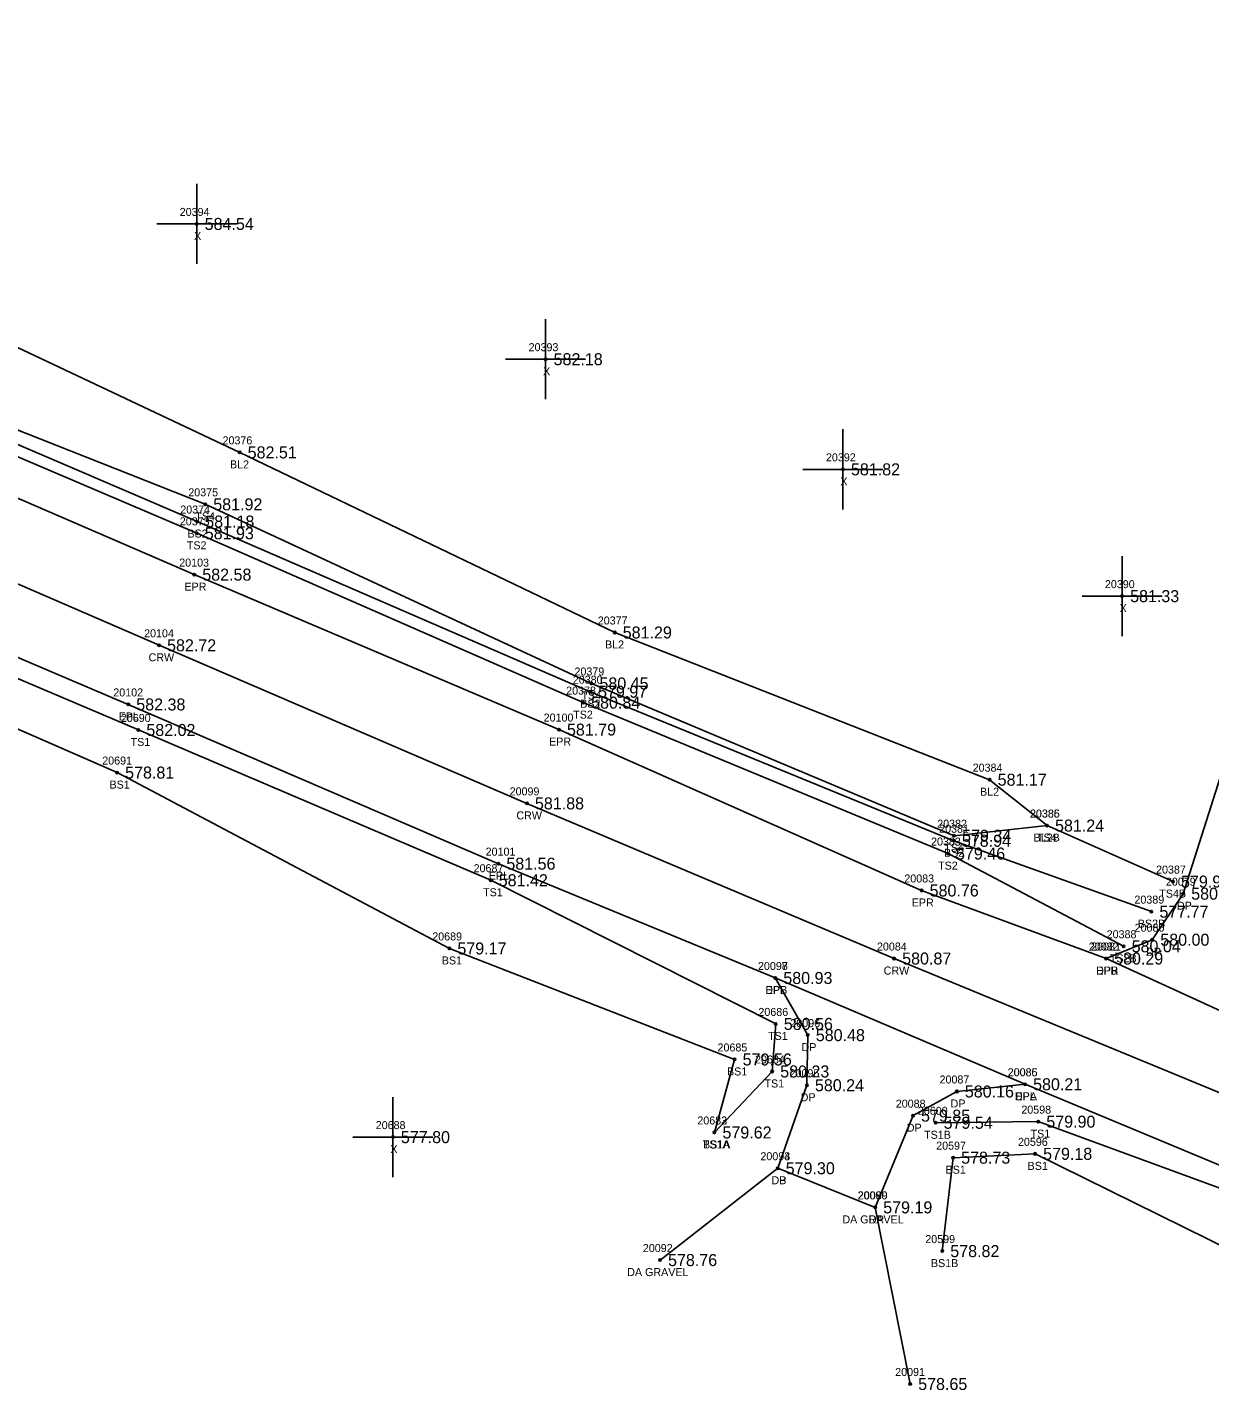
# Model space of a CAD drawing. Extents: x 1664837 to 1666270, y 987403 to 988245.
# Drawn here: x 1664992.8 to 1665140.5, y 987882.7 to 988053 of the extents above; entities that cross this region are included whole.
import ezdxf

# ---------------------------------------------------------------- set-up
doc = ezdxf.new("R2010")
doc.units = 0
for name, color, linetype in [('RD_DTM_BkLn1', 7, 'Continuous'), ('RD_DTM_BkLn2', 7, 'Continuous'), ('RD_DTM_BkLn_txCode', 7, 'Continuous'), ('RD_EX_Driveway', 7, 'Continuous'), ('RD_EX_Driveway_txCode', 7, 'Continuous'), ('RD_EX_Misc', 7, 'Continuous'), ('RD_EX_Misc_txCode', 7, 'Continuous'), ('RD_EX_Road', 7, 'Continuous'), ('RD_EX_Road_txCode', 7, 'Continuous'), ('RD_EX_TX_Driveway_ELEV', 7, 'Continuous'), ('RD_EX_TX_Misc_ELEV', 7, 'Continuous'), ('RD_EX_TX_Road_ELEV', 7, 'Continuous'), ('RD_HC_Survey_ELEV', 7, 'Continuous'), ('RD_HC_Survey_txCode', 7, 'Continuous'), ('RD_SMD_Locator', 7, 'Continuous')]:
    doc.layers.add(name, color=color, linetype=linetype)

msp = doc.modelspace()

# ---------------------------------------------------------------- linework, layer by layer
at = {"layer": 'RD_DTM_BkLn1'}
for points in [[(1664897.55, 988053.04), (1664929.93, 988036.23), (1664960.35, 988021.59), (1664980.14, 988018.4), (1665019.3, 987999.93), (1665066.16, 987977.43), (1665113, 987959.04), (1665120.17, 987953.31)], [(1665502.18, 987767.43), (1665469.18, 987781.68), (1665423.29, 987801.23), (1665377.17, 987820.37), (1665331.28, 987839.54), (1665285.44, 987859.03), (1665239.3, 987878.58), (1665193.14, 987897.86), (1665147.41, 987917.57), (1665101.07, 987936.7), (1665055.19, 987956.08), (1665009.23, 987975.83), (1664963.42, 987995.66), (1664917.15, 988015.07), (1664871.41, 988034.69)]]:
    msp.add_lwpolyline(points, dxfattribs=at)
at = {"layer": 'RD_DTM_BkLn2'}
for points in [[(1665078.62, 987914.97), (1665085.83, 987922.59), (1665086.28, 987928.53), (1665050.67, 987946.48), (1665006.64, 987965.25), (1664958.17, 987985.85), (1664911.17, 988003.87), (1664865.99, 988023.87)], [(1665078.62, 987914.97), (1665081.14, 987924.09), (1665045.5, 987937.96), (1665003.99, 987959.93), (1664956.22, 987980.82), (1664908.92, 987999.6), (1664864.19, 988020.45)], [(1664946.01, 988020.8), (1664948.9, 988017.98), (1664969.38, 988008.82), (1665013.94, 987989.82), (1665062.21, 987968.67), (1665107.8, 987949.81), (1665129.74, 987938.23)], [(1664946.01, 988020.8), (1664949.25, 988019.2), (1664969.82, 988010.25), (1665014, 987991.29), (1665063.08, 987970.03), (1665108.53, 987951.41), (1665133.21, 987942.56)], [(1664946.01, 988020.8), (1664949.87, 988020.34), (1664970.31, 988011.11), (1665015, 987993.44), (1665063.25, 987971.06), (1665108.56, 987952.04), (1665120.17, 987953.31), (1665135.91, 987946.31)], [(1665497.35, 987756.86), (1665493.15, 987755.47), (1665489.09, 987748.98), (1665474.07, 987754.55), (1665461.3, 987759.68), (1665416.12, 987784.47), (1665369.46, 987807.94), (1665325.7, 987826.1), (1665279.41, 987845.24), (1665231.91, 987860.98), (1665183.47, 987888.09), (1665142.67, 987907.67), (1665119.08, 987916.32), (1665106.25, 987916.18)], [(1665485.84, 987738.32), (1665468.07, 987746.27), (1665459.94, 987754.9), (1665412.19, 987777.99), (1665366.38, 987802.17), (1665323.99, 987821.27), (1665274.79, 987834.22), (1665225.63, 987853.6), (1665180.43, 987876.62), (1665166.98, 987883.63), (1665152.71, 987895.52), (1665118.68, 987912.3), (1665108.44, 987911.82), (1665107.08, 987900.15)]]:
    msp.add_lwpolyline(points, dxfattribs=at)
at = {"layer": 'RD_EX_Driveway'}
for p, q in [((1665071.82, 987899.03), (1665086.52, 987910.5)), ((1665098.7, 987905.61), (1665103.07, 987883.55))]:
    msp.add_line(p, q, dxfattribs=at)
for points in [[(1665149.43, 987977.47), (1665143.55, 987964.8), (1665137.18, 987944.8), (1665133.32, 987939.05), (1665127.55, 987936.7)], [(1665117.43, 987920.99), (1665108.9, 987920.09), (1665103.43, 987917.07), (1665098.7, 987905.61), (1665086.52, 987910.5), (1665090.17, 987920.87), (1665090.28, 987927.13), (1665086.22, 987934.27)]]:
    msp.add_lwpolyline(points, dxfattribs=at)
at = {"layer": 'RD_EX_Misc'}
for p, q in [((1665013.93, 988023.47), (1665013.93, 988033.47)), ((1665008.93, 988028.47), (1665018.93, 988028.47)), ((1665057.52, 988006.57), (1665057.52, 988016.57)), ((1665052.52, 988011.57), (1665062.52, 988011.57)), ((1665094.67, 987992.81), (1665094.67, 988002.81)), ((1665089.67, 987997.81), (1665099.67, 987997.81)), ((1665129.55, 987976.97), (1665129.55, 987986.97)), ((1665124.55, 987981.97), (1665134.55, 987981.97)), ((1665038.44, 987909.39), (1665038.44, 987919.39)), ((1665033.44, 987914.39), (1665043.44, 987914.39))]:
    msp.add_line(p, q, dxfattribs=at)
at = {"layer": 'RD_EX_Road'}
for points in [[(1665506.06, 987776.52), (1665471.95, 987789.57), (1665426.52, 987809.19), (1665380.33, 987828.78), (1665335.61, 987847.53), (1665288.25, 987866.82), (1665242.34, 987886.56), (1665197.07, 987906.16), (1665152.2, 987925.43), (1665127.55, 987936.7), (1665104.5, 987945.2), (1665059.19, 987965.3), (1665013.63, 987984.66), (1664966.38, 988005.06), (1664921.66, 988023.83), (1664875.55, 988043.8)], [(1665498.75, 987759.37), (1665465.87, 987774.2), (1665419.78, 987793.88), (1665373.62, 987813.14), (1665327.95, 987832.31), (1665281.42, 987852.3), (1665236.13, 987871.34), (1665189.6, 987890.71), (1665143.92, 987909.97), (1665117.43, 987920.99), (1665086.22, 987934.27), (1665051.62, 987948.55), (1665005.38, 987968.44), (1664960.17, 987987.67), (1664913.53, 988007.62), (1664868.21, 988026.81)]]:
    msp.add_lwpolyline(points, dxfattribs=at)
at = {"layer": 'RD_SMD_Locator'}
for centre in [(1665013.93, 988028.47), (1665057.52, 988011.57), (1665019.3, 987999.93), (1665094.67, 987997.81), (1665015, 987993.44), (1665014, 987991.29), (1665013.94, 987989.82), (1665013.63, 987984.66), (1665129.55, 987981.97), (1665009.23, 987975.83), (1665066.16, 987977.43), (1665063.25, 987971.06), (1665063.08, 987970.03), (1665005.38, 987968.44), (1665062.21, 987968.67), (1665006.64, 987965.25), (1665059.19, 987965.3), (1665003.99, 987959.93), (1665113, 987959.04), (1665055.19, 987956.08), (1665108.56, 987952.04), (1665120.17, 987953.31), (1665120.17, 987953.31), (1665108.53, 987951.41), (1665051.62, 987948.55), (1665107.8, 987949.81), (1665050.67, 987946.48), (1665104.5, 987945.2), (1665135.91, 987946.31), (1665137.18, 987944.8), (1665133.21, 987942.56), (1665133.32, 987939.05), (1665045.5, 987937.96), (1665101.07, 987936.7), (1665127.55, 987936.7), (1665127.55, 987936.7), (1665129.74, 987938.23), (1665086.22, 987934.27), (1665086.22, 987934.27), (1665086.28, 987928.53), (1665090.28, 987927.13), (1665081.14, 987924.09), (1665085.83, 987922.59), (1665090.17, 987920.87), (1665108.9, 987920.09), (1665117.43, 987920.99), (1665117.43, 987920.99), (1665103.43, 987917.07), (1665106.25, 987916.18), (1665119.08, 987916.32), (1665078.62, 987914.97), (1665078.62, 987914.97), (1665038.44, 987914.39), (1665108.44, 987911.82), (1665118.68, 987912.3), (1665086.52, 987910.5), (1665086.52, 987910.5), (1665098.7, 987905.61), (1665098.7, 987905.61), (1665107.08, 987900.15), (1665071.82, 987899.03), (1665103.07, 987883.55)]:
    msp.add_circle(centre, 0.15, dxfattribs=at)

# ---------------------------------------------------------------- texts
at = {"layer": 'RD_DTM_BkLn_txCode'}
for s, p in [('20376', (1665017.16, 988000.93)), ('BL2', (1665018.09, 987997.93)), ('20375', (1665012.88, 987994.44)), ('20374', (1665011.88, 987992.29)), ('20373', (1665011.82, 987990.82)), ('TS4', (1665013.76, 987991.44)), ('BS2', (1665012.77, 987989.29)), ('TS2', (1665012.7, 987987.82)), ('20377', (1665064.04, 987978.43)), ('BL2', (1665064.95, 987975.43)), ('20379', (1665061.13, 987972.06)), ('20380', (1665060.92, 987971.03)), ('20378', (1665060.09, 987969.67)), ('TS4', (1665062, 987969.06)), ('TS2', (1665060.97, 987966.67)), ('BS2', (1665061.85, 987968.03)), ('20690', (1665004.46, 987966.25)), ('TS1', (1665005.68, 987963.25)), ('20691', (1665002.13, 987960.93)), ('20384', (1665110.88, 987960.04)), ('BS1', (1665003.04, 987957.93)), ('BL2', (1665111.8, 987957.04)), ('20382', (1665106.45, 987953.04)), ('20386', (1665118.03, 987954.31)), ('20385', (1665118.05, 987954.31)), ('20381', (1665106.69, 987952.41)), ('BL2B', (1665118.49, 987951.31)), ('TS4', (1665118.92, 987951.31)), ('20383', (1665105.68, 987950.81)), ('TS4', (1665107.32, 987950.04)), ('BS2', (1665107.3, 987949.41)), ('TS2', (1665106.56, 987947.81)), ('20687', (1665048.53, 987947.48)), ('20387', (1665133.79, 987947.31)), ('TS1', (1665049.71, 987944.48)), ('TS4B', (1665134.19, 987944.31)), ('20389', (1665131.09, 987943.56)), ('20388', (1665127.62, 987939.23)), ('BS2B', (1665131.51, 987940.56)), ('20689', (1665043.36, 987938.96)), ('BS1', (1665044.55, 987935.96)), ('TS2B', (1665128.02, 987936.23)), ('20686', (1665084.11, 987929.53)), ('TS1', (1665085.32, 987926.53)), ('20685', (1665079, 987925.09)), ('20684', (1665083.69, 987923.59)), ('BS1', (1665080.19, 987922.09)), ('TS1', (1665084.87, 987920.59)), ('20600', (1665104.03, 987917.18)), ('20598', (1665116.96, 987917.32)), ('20682', (1665076.48, 987915.97)), ('20683', (1665076.48, 987915.97)), ('TS1B', (1665104.81, 987914.18)), ('TS1', (1665118.11, 987914.32)), ('TS1A', (1665077.17, 987912.97)), ('BS1A', (1665077.19, 987912.97)), ('20597', (1665106.32, 987912.82)), ('20596', (1665116.54, 987913.3)), ('BS1', (1665117.74, 987910.3)), ('BS1', (1665107.49, 987909.82)), ('20599', (1665104.96, 987901.15)), ('BS1B', (1665105.66, 987898.15))]:
    msp.add_text(s, height=1, dxfattribs=at).set_placement(p)
at = {"layer": 'RD_EX_Driveway_txCode'}
for s, p in [('20079', (1665135.02, 987945.8)), ('DP', (1665136.4, 987942.8)), ('20080', (1665131.12, 987940.05)), ('20081', (1665125.68, 987937.7)), ('DP', (1665132.54, 987937.05)), ('20097', (1665084.06, 987935.27)), ('DPB', (1665126.3, 987934.7)), ('DPB', (1665084.97, 987932.27)), ('20096', (1665088.1, 987928.13)), ('DP', (1665089.5, 987925.13)), ('20095', (1665088.01, 987921.87)), ('20087', (1665106.74, 987921.09)), ('20086', (1665115.25, 987921.99)), ('DP', (1665089.39, 987918.87)), ('DPA', (1665116.16, 987918.99)), ('20088', (1665101.27, 987918.07)), ('DP', (1665108.12, 987918.09)), ('DP', (1665102.65, 987915.07)), ('20093', (1665084.36, 987911.5)), ('20094', (1665084.36, 987911.5)), ('DB', (1665085.74, 987908.5)), ('DP', (1665085.74, 987908.5)), ('20090', (1665096.5, 987906.61)), ('20089', (1665096.54, 987906.61)), ('DA GRAVEL', (1665094.6, 987903.61)), ('DP', (1665097.92, 987903.61)), ('20092', (1665069.67, 987900.03)), ('DA GRAVEL', (1665067.72, 987897.03)), ('20091', (1665101.2, 987884.55))]:
    msp.add_text(s, height=1, dxfattribs=at).set_placement(p)
at = {"layer": 'RD_EX_Misc_txCode'}
for s, p in [('20394', (1665011.81, 988029.47)), ('X', (1665013.61, 988026.47)), ('20393', (1665055.4, 988012.57)), ('X', (1665057.21, 988009.57)), ('20392', (1665092.55, 987998.81)), ('X', (1665094.35, 987995.81)), ('20390', (1665127.4, 987982.97)), ('X', (1665129.24, 987979.97)), ('20688', (1665036.3, 987915.39)), ('X', (1665038.13, 987912.39))]:
    msp.add_text(s, height=1, dxfattribs=at).set_placement(p)
at = {"layer": 'RD_EX_Road_txCode'}
for s, p in [('20103', (1665011.75, 987985.66)), ('EPR', (1665012.4, 987982.66)), ('20102', (1665003.51, 987969.44)), ('EPL', (1665004.18, 987966.44)), ('20100', (1665057.28, 987966.3)), ('EPR', (1665057.96, 987963.3)), ('20101', (1665050.03, 987949.55)), ('EPL', (1665050.42, 987946.55)), ('20083', (1665102.34, 987946.2)), ('EPR', (1665103.27, 987943.2)), ('20082', (1665125.39, 987937.7)), ('20098', (1665084.06, 987935.27)), ('EPR', (1665126.32, 987934.7)), ('EPL', (1665085.01, 987932.27)), ('20085', (1665115.27, 987921.99)), ('EPL', (1665116.22, 987918.99))]:
    msp.add_text(s, height=1, dxfattribs=at).set_placement(p)
at = {"layer": 'RD_EX_TX_Driveway_ELEV'}
for s, p in [('580.01', (1665138.18, 987944.05)), ('580.00', (1665134.32, 987938.3)), ('580.29', (1665128.55, 987935.95)), ('580.93', (1665087.22, 987933.52)), ('580.48', (1665091.28, 987926.38)), ('580.24', (1665091.17, 987920.12)), ('580.21', (1665118.43, 987920.24)), ('580.16', (1665109.9, 987919.34)), ('579.85', (1665104.43, 987916.32)), ('579.30', (1665087.52, 987909.75)), ('579.30', (1665087.52, 987909.75)), ('579.19', (1665099.7, 987904.86)), ('579.19', (1665099.7, 987904.86)), ('578.76', (1665072.82, 987898.28)), ('578.65', (1665104.07, 987882.8))]:
    msp.add_text(s, height=1.5, dxfattribs=at).set_placement(p)
at = {"layer": 'RD_EX_TX_Misc_ELEV'}
for s, p in [('584.54', (1665014.93, 988027.72)), ('582.18', (1665058.52, 988010.82)), ('582.51', (1665020.3, 987999.18)), ('581.82', (1665095.67, 987997.06)), ('581.92', (1665016, 987992.69)), ('581.18', (1665015, 987990.54)), ('581.93', (1665014.94, 987989.07)), ('581.33', (1665130.55, 987981.22)), ('581.29', (1665067.16, 987976.68)), ('580.45', (1665064.25, 987970.31)), ('580.84', (1665063.21, 987967.92)), ('579.97', (1665064.08, 987969.28)), ('582.02', (1665007.64, 987964.5)), ('578.81', (1665004.99, 987959.18)), ('581.17', (1665114, 987958.29)), ('581.24', (1665121.17, 987952.56)), ('581.24', (1665121.17, 987952.56)), ('578.94', (1665109.53, 987950.66)), ('579.34', (1665109.56, 987951.29)), ('579.46', (1665108.8, 987949.06)), ('581.42', (1665051.67, 987945.73)), ('579.96', (1665136.91, 987945.56)), ('577.77', (1665134.21, 987941.81)), ('579.17', (1665046.5, 987937.21)), ('580.04', (1665130.74, 987937.48)), ('580.56', (1665087.28, 987927.78)), ('579.56', (1665082.14, 987923.34)), ('580.23', (1665086.83, 987921.84)), ('579.54', (1665107.25, 987915.43)), ('579.90', (1665120.08, 987915.57)), ('577.80', (1665039.44, 987913.64)), ('579.62', (1665079.62, 987914.22)), ('579.62', (1665079.62, 987914.22)), ('579.18', (1665119.68, 987911.55)), ('578.73', (1665109.44, 987911.07)), ('578.82', (1665108.08, 987899.4))]:
    msp.add_text(s, height=1.5, dxfattribs=at).set_placement(p)
at = {"layer": 'RD_EX_TX_Road_ELEV'}
for s, p in [('582.58', (1665014.63, 987983.91)), ('582.38', (1665006.38, 987967.69)), ('581.79', (1665060.19, 987964.55)), ('581.56', (1665052.62, 987947.8)), ('580.76', (1665105.5, 987944.45)), ('580.29', (1665128.55, 987935.95)), ('580.93', (1665087.22, 987933.52)), ('580.21', (1665118.43, 987920.24))]:
    msp.add_text(s, height=1.5, dxfattribs=at).set_placement(p)
at = {"layer": 'RD_HC_Survey_ELEV'}
for s, p in [('582.72', (1665010.23, 987975.08)), ('581.88', (1665056.19, 987955.33)), ('580.87', (1665102.07, 987935.95))]:
    msp.add_text(s, height=1.5, dxfattribs=at).set_placement(p)
at = {"layer": 'RD_HC_Survey_txCode'}
for s, p in [('20104', (1665007.36, 987976.83)), ('CRW', (1665007.92, 987973.83)), ('20099', (1665053.03, 987957.08)), ('CRW', (1665053.87, 987954.08)), ('20084', (1665098.92, 987937.7)), ('CRW', (1665099.76, 987934.7))]:
    msp.add_text(s, height=1, dxfattribs=at).set_placement(p)

doc.saveas('drawing.dxf')
